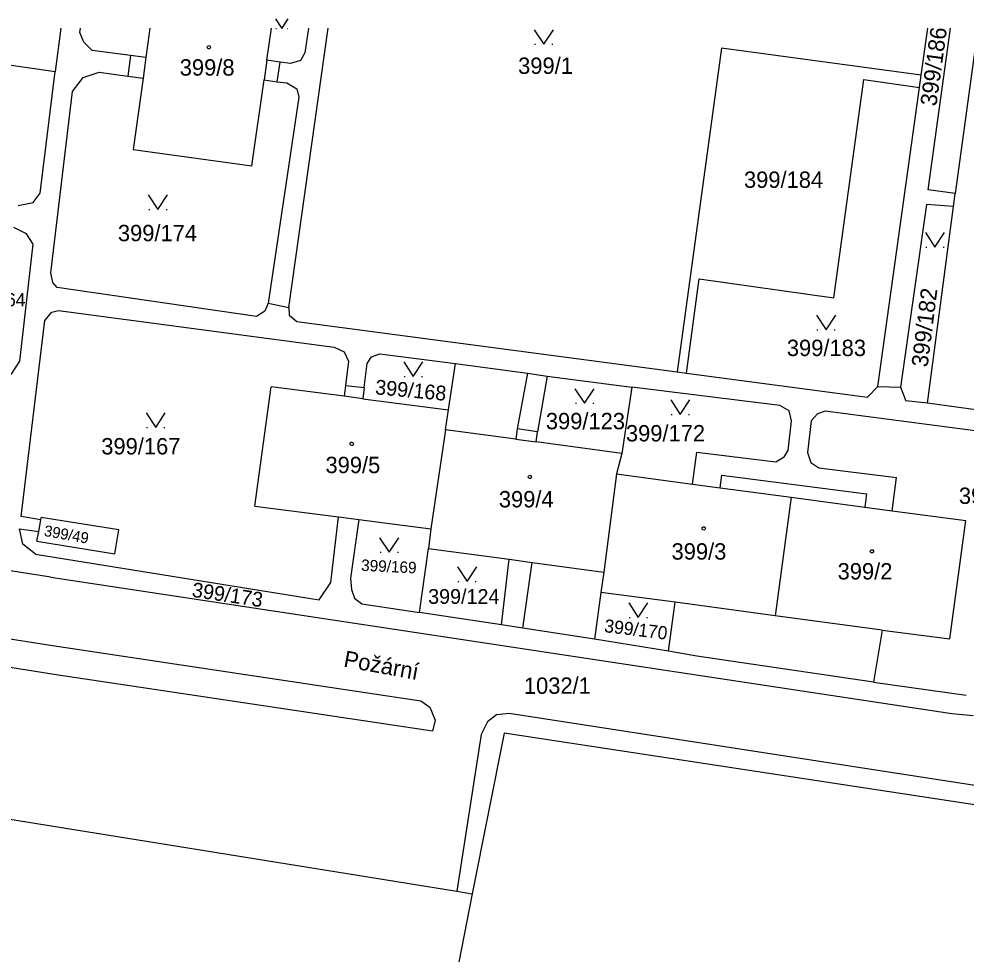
# Model space of a CAD drawing. Extents: x -851495 to -851222, y -1010479 to -1010202.
# Drawn here: x -851431.6 to -851333.3, y -1010299.4 to -1010202.3 of the extents above; entities that cross this region are included whole.
import ezdxf

# ---------------------------------------------------------------- set-up
doc = ezdxf.new("R2010")
doc.units = 0
for name, color, linetype in [('1', 7, 'Continuous'), ('12', 7, 'Continuous'), ('2', 7, 'Continuous'), ('3', 7, 'Continuous'), ('4', 7, 'Continuous'), ('5', 7, 'Continuous'), ('7', 7, 'Continuous')]:
    doc.layers.add(name, color=color, linetype=linetype)

# ---------------------------------------------------------------- blocks, each defined once
blk = doc.blocks.new('314')
for p, q in [((-0.95, 0), (-0.85, 0)), ((0.85, 0), (0.95, 0))]:
    blk.add_line(p, q)
blk.add_lwpolyline([(-1, 1.5), (0, 0), (1, 1.5)])
blk = doc.blocks.new('404')
blk.add_lwpolyline([(0, 0.17), (0.1, 0.15), (0.15, 0.06), (0.17, 0), (0.15, -0.09), (0.07, -0.16), (0, -0.17), (-0.09, -0.14), (-0.15, -0.08), (-0.17, 0), (-0.15, 0.09), (-0.07, 0.16), (0, 0.17)])

msp = doc.modelspace()

# ---------------------------------------------------------------- linework, layer by layer
at = {"layer": '1'}
for p, q in [((-851427.24, -1010203.26), (-851427.84, -1010207.75)), ((-851425.27, -1010203.69), (-851425.21, -1010203.26)), ((-851424.84, -1010204.71), (-851425.27, -1010203.69)), ((-851417.98, -1010203.26), (-851418.4, -1010206.31)), ((-851405.84, -1010206.57), (-851405.37, -1010203.26)), ((-851403.58, -1010232.24), (-851399.48, -1010203.26)), ((-851401.54, -1010203.26), (-851401.91, -1010205.82)), ((-851337.91, -1010208.14), (-851337.22, -1010203.26)), ((-851337.19, -1010220.03), (-851334.86, -1010203.26)), ((-851332.03, -1010203.26), (-851334.4, -1010220.43)), ((-851423.99, -1010205.57), (-851424.84, -1010204.71)), ((-851441.63, -1010205.73), (-851427.84, -1010207.75)), ((-851419.99, -1010206.1), (-851423.99, -1010205.57)), ((-851401.91, -1010205.82), (-851402.36, -1010206.61)), ((-851358.63, -1010205.33), (-851363.26, -1010238.93)), ((-851337.91, -1010208.14), (-851358.63, -1010205.33)), ((-851419.99, -1010206.1), (-851420.28, -1010208.23)), ((-851418.4, -1010206.31), (-851419.99, -1010206.1)), ((-851404.46, -1010206.77), (-851405.84, -1010206.57)), ((-851404.76, -1010208.81), (-851404.46, -1010206.77)), ((-851403.39, -1010206.93), (-851404.46, -1010206.77)), ((-851402.36, -1010206.61), (-851403.39, -1010206.93)), ((-851429.37, -1010220.39), (-851427.84, -1010207.75)), ((-851424.92, -1010208.36), (-851423.26, -1010207.82)), ((-851423.26, -1010207.82), (-851420.28, -1010208.23)), ((-851426.01, -1010209.81), (-851424.92, -1010208.36)), ((-851420.28, -1010208.23), (-851418.7, -1010208.45)), ((-851418.7, -1010208.45), (-851419.72, -1010215.85)), ((-851407.41, -1010217.54), (-851406.13, -1010208.61)), ((-851406.13, -1010208.61), (-851404.76, -1010208.81)), ((-851404.76, -1010208.81), (-851403.76, -1010208.93)), ((-851403.76, -1010208.93), (-851402.74, -1010209.55)), ((-851346.98, -1010231.23), (-851343.87, -1010208.58)), ((-851343.87, -1010208.58), (-851338.09, -1010209.4)), ((-851338.09, -1010209.4), (-851337.91, -1010208.14)), ((-851428.26, -1010228.64), (-851426.01, -1010209.81)), ((-851402.74, -1010209.55), (-851402.53, -1010210.42)), ((-851342.42, -1010240.44), (-851338.09, -1010209.4)), ((-851402.53, -1010210.42), (-851405.7, -1010231.81)), ((-851419.72, -1010215.85), (-851407.41, -1010217.54)), ((-851430.11, -1010221.35), (-851429.37, -1010220.39)), ((-851334.4, -1010220.43), (-851337.19, -1010220.03)), ((-851334.57, -1010221.77), (-851334.4, -1010220.43)), ((-851431.65, -1010221.67), (-851430.11, -1010221.35)), ((-851337.35, -1010221.55), (-851340.07, -1010240.53)), ((-851334.57, -1010221.77), (-851337.35, -1010221.55)), ((-851337.25, -1010242.19), (-851334.57, -1010221.77)), ((-851430.8, -1010224.61), (-851432.12, -1010223.96)), ((-851430.12, -1010225.69), (-851430.8, -1010224.61)), ((-851431.5, -1010237.81), (-851430.12, -1010225.69)), ((-851428.05, -1010229.65), (-851428.26, -1010228.64)), ((-851362.27, -1010239.06), (-851360.98, -1010229.29)), ((-851360.98, -1010229.29), (-851346.98, -1010231.23)), ((-851427.63, -1010230.16), (-851428.05, -1010229.65)), ((-851406.92, -1010233.17), (-851427.63, -1010230.16)), ((-851428.17, -1010232.75), (-851427.49, -1010232.55)), ((-851427.49, -1010232.55), (-851398.86, -1010236.38)), ((-851405.7, -1010231.81), (-851406.07, -1010232.62)), ((-851405.7, -1010231.81), (-851403.58, -1010232.24)), ((-851403.58, -1010232.24), (-851403.53, -1010233.06)), ((-851428.88, -1010233.6), (-851428.17, -1010232.75)), ((-851406.07, -1010232.62), (-851406.92, -1010233.17)), ((-851403.53, -1010233.06), (-851402.72, -1010233.7)), ((-851431.36, -1010253.95), (-851428.88, -1010233.6)), ((-851402.72, -1010233.7), (-851363.26, -1010238.93)), ((-851398.86, -1010236.38), (-851397.82, -1010236.86)), ((-851397.82, -1010236.86), (-851397.36, -1010237.82)), ((-851395.43, -1010238.06), (-851394.98, -1010237.37)), ((-851394.98, -1010237.37), (-851394.11, -1010237.07)), ((-851394.11, -1010237.07), (-851386.25, -1010238.05)), ((-851432.4, -1010239.22), (-851431.5, -1010237.81)), ((-851397.36, -1010237.82), (-851397.68, -1010240.33)), ((-851395.74, -1010240.55), (-851395.43, -1010238.06)), ((-851386.99, -1010242.87), (-851386.25, -1010238.05)), ((-851386.25, -1010238.05), (-851378.8, -1010239.08)), ((-851378.8, -1010239.08), (-851376.76, -1010239.36)), ((-851376.76, -1010239.36), (-851367.97, -1010240.51)), ((-851363.26, -1010238.93), (-851362.27, -1010239.06)), ((-851362.27, -1010239.06), (-851343.5, -1010241.57)), ((-851397.68, -1010240.33), (-851397.81, -1010241.47)), ((-851397.68, -1010240.33), (-851395.74, -1010240.55)), ((-851343.5, -1010241.57), (-851342.42, -1010240.44)), ((-851342.42, -1010240.44), (-851340.07, -1010240.53)), ((-851407.08, -1010252.86), (-851405.41, -1010240.49)), ((-851397.81, -1010241.47), (-851405.41, -1010240.49)), ((-851395.74, -1010240.55), (-851395.88, -1010241.72)), ((-851367.97, -1010240.51), (-851368.98, -1010247.4)), ((-851352.59, -1010242.43), (-851367.97, -1010240.51)), ((-851340.07, -1010240.53), (-851339.5, -1010241.93)), ((-851395.88, -1010241.72), (-851386.99, -1010242.87)), ((-851337.25, -1010242.19), (-851339.5, -1010241.93)), ((-851320.86, -1010244.4), (-851337.25, -1010242.19)), ((-851387.3, -1010244.95), (-851386.99, -1010242.87)), ((-851351.61, -1010242.96), (-851352.59, -1010242.43)), ((-851351.37, -1010244.01), (-851351.61, -1010242.96)), ((-851348.69, -1010243.28), (-851349.35, -1010244.02)), ((-851347.89, -1010243.01), (-851348.69, -1010243.28)), ((-851324.05, -1010246.13), (-851347.89, -1010243.01)), ((-851351.73, -1010247.09), (-851351.37, -1010244.01)), ((-851349.35, -1010244.02), (-851349.73, -1010247.3)), ((-851387.3, -1010244.95), (-851388.82, -1010255.24)), ((-851380, -1010245.93), (-851387.3, -1010244.95)), ((-851379.86, -1010244.86), (-851380, -1010245.93)), ((-851377.74, -1010245.14), (-851379.86, -1010244.86)), ((-851377.88, -1010246.21), (-851377.74, -1010245.14)), ((-851368.98, -1010247.4), (-851377.88, -1010246.21)), ((-851361.66, -1010250.58), (-851361.22, -1010247.28)), ((-851361.22, -1010247.28), (-851352.99, -1010248.27)), ((-851352.13, -1010247.76), (-851351.73, -1010247.09)), ((-851349.73, -1010247.3), (-851349.36, -1010248.33)), ((-851368.98, -1010247.4), (-851369.55, -1010249.53)), ((-851352.99, -1010248.27), (-851352.13, -1010247.76)), ((-851349.36, -1010248.33), (-851348.53, -1010248.89)), ((-851348.53, -1010248.89), (-851340.48, -1010249.89)), ((-851369.55, -1010249.53), (-851370.86, -1010259.72)), ((-851369.55, -1010249.53), (-851361.66, -1010250.58)), ((-851340.94, -1010253.34), (-851340.48, -1010249.89)), ((-851361.66, -1010250.58), (-851358.79, -1010250.97)), ((-851358.79, -1010250.97), (-851351.41, -1010251.95)), ((-851351.41, -1010251.95), (-851353.06, -1010264.24)), ((-851351.41, -1010251.95), (-851343.78, -1010252.96)), ((-851407.08, -1010252.86), (-851398.4, -1010253.99)), ((-851343.78, -1010252.96), (-851340.94, -1010253.34)), ((-851429.32, -1010254.3), (-851431.36, -1010253.95)), ((-851429.32, -1010254.3), (-851429.27, -1010254.04)), ((-851421.23, -1010255.34), (-851429.27, -1010254.04)), ((-851399.21, -1010260.78), (-851398.4, -1010253.99)), ((-851398.4, -1010253.99), (-851396.31, -1010254.26)), ((-851340.94, -1010253.34), (-851333.28, -1010254.36)), ((-851429.53, -1010255.5), (-851429.32, -1010254.3)), ((-851396.31, -1010254.26), (-851397.15, -1010260.35)), ((-851396.31, -1010254.26), (-851388.82, -1010255.24)), ((-851334.93, -1010266.66), (-851333.28, -1010254.36)), ((-851428.27, -1010260.23), (-851454.53, -1010256.16)), ((-851431.17, -1010256.82), (-851431.52, -1010255.22)), ((-851431.52, -1010255.22), (-851429.53, -1010255.5)), ((-851429.72, -1010256.52), (-851429.53, -1010255.5)), ((-851421.63, -1010257.83), (-851421.23, -1010255.34)), ((-851388.82, -1010255.24), (-851389.07, -1010257.26)), ((-851429.88, -1010257.84), (-851431.17, -1010256.82)), ((-851429.72, -1010256.52), (-851421.63, -1010257.83)), ((-851429.88, -1010257.84), (-851400.41, -1010262.59)), ((-851389.99, -1010263.92), (-851389.07, -1010257.26)), ((-851389.07, -1010257.26), (-851380.68, -1010258.39)), ((-851380.68, -1010258.39), (-851378.29, -1010258.71)), ((-851378.29, -1010258.71), (-851370.86, -1010259.72)), ((-851370.86, -1010259.72), (-851371.19, -1010261.82)), ((-851428.27, -1010260.23), (-851334.74, -1010274.41)), ((-851400.41, -1010262.59), (-851399.21, -1010260.78)), ((-851397.15, -1010260.35), (-851397.06, -1010261.53)), ((-851397.06, -1010261.53), (-851396.75, -1010262.43)), ((-851371.19, -1010261.82), (-851371.84, -1010266.68)), ((-851363.46, -1010262.85), (-851371.19, -1010261.82)), ((-851396.75, -1010262.43), (-851395.99, -1010263.02)), ((-851395.99, -1010263.02), (-851389.99, -1010263.92)), ((-851364.16, -1010267.91), (-851363.46, -1010262.85)), ((-851353.06, -1010264.24), (-851363.46, -1010262.85)), ((-851381.48, -1010265.18), (-851389.99, -1010263.92)), ((-851379.26, -1010265.55), (-851381.48, -1010265.18)), ((-851371.84, -1010266.68), (-851379.26, -1010265.55)), ((-851341.96, -1010265.73), (-851342.87, -1010271.15)), ((-851341.96, -1010265.73), (-851334.93, -1010266.66)), ((-851364.16, -1010267.91), (-851371.84, -1010266.68)), ((-851361.19, -1010268.43), (-851364.16, -1010267.91)), ((-851342.87, -1010271.15), (-851361.19, -1010268.43)), ((-851342.87, -1010271.15), (-851333.23, -1010272.48)), ((-851334.74, -1010274.41), (-851332.53, -1010274.61)), ((-851381.22, -1010276.44), (-851384.52, -1010293.11)), ((-851307.21, -1010287.72), (-851381.22, -1010276.44)), ((-851457.47, -1010281.32), (-851386.12, -1010292.85)), ((-851384.52, -1010293.11), (-851392.95, -1010335.63)), ((-851386.12, -1010292.85), (-851384.52, -1010293.11))]:
    msp.add_line(p, q, dxfattribs=at)
at = {"layer": '12'}
for p, q in [((-851417.98, -1010203.26), (-851418.4, -1010206.31)), ((-851405.84, -1010206.57), (-851405.37, -1010203.26)), ((-851418.4, -1010206.31), (-851418.7, -1010208.45)), ((-851405.84, -1010206.57), (-851406.13, -1010208.61)), ((-851418.7, -1010208.45), (-851419.72, -1010215.85)), ((-851407.41, -1010217.54), (-851406.13, -1010208.61)), ((-851419.72, -1010215.85), (-851407.41, -1010217.54)), ((-851407.08, -1010252.86), (-851405.41, -1010240.49)), ((-851397.81, -1010241.47), (-851405.41, -1010240.49)), ((-851395.88, -1010241.72), (-851397.81, -1010241.47)), ((-851395.88, -1010241.72), (-851386.99, -1010242.87)), ((-851387.3, -1010244.95), (-851386.99, -1010242.87)), ((-851387.3, -1010244.95), (-851388.82, -1010255.24)), ((-851387.3, -1010244.95), (-851388.82, -1010255.24)), ((-851380, -1010245.93), (-851387.3, -1010244.95)), ((-851380, -1010245.93), (-851377.88, -1010246.21)), ((-851368.98, -1010247.4), (-851377.88, -1010246.21)), ((-851368.98, -1010247.4), (-851369.55, -1010249.53)), ((-851369.55, -1010249.53), (-851370.86, -1010259.72)), ((-851369.55, -1010249.53), (-851370.86, -1010259.72)), ((-851369.55, -1010249.53), (-851361.66, -1010250.58)), ((-851361.66, -1010250.58), (-851358.79, -1010250.97)), ((-851358.79, -1010250.97), (-851351.41, -1010251.95)), ((-851351.41, -1010251.95), (-851343.78, -1010252.96)), ((-851407.08, -1010252.86), (-851398.4, -1010253.99)), ((-851343.78, -1010252.96), (-851340.94, -1010253.34)), ((-851398.4, -1010253.99), (-851396.31, -1010254.26)), ((-851340.94, -1010253.34), (-851333.28, -1010254.36)), ((-851396.31, -1010254.26), (-851388.82, -1010255.24)), ((-851334.93, -1010266.66), (-851333.28, -1010254.36)), ((-851388.82, -1010255.24), (-851389.07, -1010257.26)), ((-851389.07, -1010257.26), (-851380.68, -1010258.39)), ((-851380.68, -1010258.39), (-851378.29, -1010258.71)), ((-851378.29, -1010258.71), (-851370.86, -1010259.72)), ((-851370.86, -1010259.72), (-851371.19, -1010261.82)), ((-851363.46, -1010262.85), (-851371.19, -1010261.82)), ((-851353.06, -1010264.24), (-851363.46, -1010262.85)), ((-851341.96, -1010265.73), (-851353.06, -1010264.24)), ((-851341.96, -1010265.73), (-851334.93, -1010266.66))]:
    msp.add_line(p, q, dxfattribs=at)
at = {"layer": '4'}
for p, q in [((-851418.4, -1010206.31), (-851418.7, -1010208.45)), ((-851405.84, -1010206.57), (-851406.13, -1010208.61)), ((-851378.8, -1010239.08), (-851379.86, -1010244.86)), ((-851376.76, -1010239.36), (-851377.74, -1010245.14)), ((-851395.88, -1010241.72), (-851397.81, -1010241.47)), ((-851380, -1010245.93), (-851377.88, -1010246.21)), ((-851358.79, -1010250.97), (-851358.61, -1010249.66)), ((-851358.61, -1010249.66), (-851343.59, -1010251.58)), ((-851343.59, -1010251.58), (-851343.78, -1010252.96)), ((-851381.48, -1010265.18), (-851380.68, -1010258.39)), ((-851379.26, -1010265.55), (-851378.29, -1010258.71)), ((-851447.98, -1010264.26), (-851428.1, -1010267.33)), ((-851341.96, -1010265.73), (-851353.06, -1010264.24)), ((-851427.72, -1010270.37), (-851448.67, -1010267.14)), ((-851428.1, -1010267.33), (-851389.87, -1010273.07)), ((-851388.66, -1010276.22), (-851427.72, -1010270.37)), ((-851389.87, -1010273.07), (-851388.92, -1010273.72)), ((-851388.92, -1010273.72), (-851388.37, -1010275.1)), ((-851382, -1010274.52), (-851382.95, -1010275.26)), ((-851380.68, -1010274.4), (-851382, -1010274.52)), ((-851327.64, -1010282.59), (-851380.68, -1010274.4)), ((-851388.37, -1010275.1), (-851388.66, -1010276.22)), ((-851382.95, -1010275.26), (-851383.59, -1010276.57)), ((-851383.59, -1010276.57), (-851386.12, -1010292.85))]:
    msp.add_line(p, q, dxfattribs=at)

# ---------------------------------------------------------------- block references
at = {"layer": '3', "xscale": 0.67, "yscale": 0.67}
msp.add_blockref('314', (-851404.29, -1010203.3), dxfattribs=at)
at = {"layer": '3'}
for p in [(-851377.1, -1010204.93), (-851417.16, -1010222.06), (-851336.48, -1010225.98), (-851347.79, -1010234.55), (-851390.64, -1010239.4), (-851372.86, -1010242.18), (-851362.92, -1010243.34), (-851417.39, -1010244.69), (-851393.14, -1010257.65), (-851385.06, -1010260.68), (-851367.28, -1010264.42)]:
    msp.add_blockref('314', p, dxfattribs=at)
at = {"layer": '5'}
for p in [(-851411.87, -1010205.23), (-851397.03, -1010246.4), (-851378.54, -1010249.84), (-851360.49, -1010255.18), (-851343.03, -1010257.56)]:
    msp.add_blockref('404', p, dxfattribs=at)

# ---------------------------------------------------------------- texts
at = {"layer": '2'}
for s, height, rotation, p in [('399/186', 1.7, 82.219, (-851336.338, -1010211.415)), ('399/182', 1.7, 82.792, (-851337.251, -1010238.502)), ('399/168', 1.53, 354.661, (-851394.65, -1010241.25)), ('399/49', 1.14, 349.848, (-851429.043, -1010255.951)), ('399/169', 1.19, 357.182, (-851396.08, -1010259.58)), ('399/173', 1.53, 351.452, (-851413.695, -1010262.271)), ('399/170', 1.36, 353.057, (-851370.87, -1010265.94)), ('1032/1', 1.7, 0.172, (-851379.16, -1010272.36))]:
    msp.add_text(s, height=height, rotation=rotation, dxfattribs=at).set_placement(p)
for s, height, p in [('399/8', 1.7, (-851414.89, -1010208.18)), ('399/1', 1.7, (-851379.76, -1010208)), ('399/184', 1.7, (-851356.31, -1010219.83)), ('399/174', 1.7, (-851421.31, -1010225.37)), ('399/164', 1.36, (-851437.48, -1010232.12)), ('399/183', 1.7, (-851351.86, -1010237.29)), ('399/123', 1.7, (-851376.88, -1010244.89)), ('399/172', 1.7, (-851368.568, -1010246.15)), ('399/167', 1.7, (-851423.038, -1010247.5)), ('399/5', 1.7, (-851399.76, -1010249.44)), ('399/4', 1.7, (-851381.76, -1010253)), ('399/171', 1.7, (-851334, -1010252.64)), ('399/3', 1.7, (-851363.83, -1010258.42)), ('399/2', 1.7, (-851346.59, -1010260.48)), ('399/124', 1.53, (-851389.1, -1010263.01))]:
    msp.add_text(s, height=height, dxfattribs=at).set_placement(p)
at = {"layer": '7'}
msp.add_text('Požární', height=1.7, rotation=349.676, dxfattribs=at).set_placement((-851397.96, -1010269.52))

doc.saveas('drawing.dxf')
